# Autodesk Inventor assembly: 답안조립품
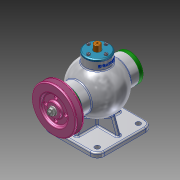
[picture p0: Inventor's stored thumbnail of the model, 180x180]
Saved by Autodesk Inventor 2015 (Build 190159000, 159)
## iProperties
Created: 2025-08
Part Number: 답안조립품
Document SubType Name: Assembly
Designer: USER
Author: USER
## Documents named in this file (15)
- C:\Users\USER\Desktop\750808V1012\답안조립품.iam
- C:\Users\USER\Desktop\750808V1012\본체.ipt
- C:\Users\USER\Desktop\750808V1012\가져온 구성요소\V-벨트풀리\V-벨트풀리.ipt
- C:\Users\USER\Desktop\750808V1012\가져온 구성요소\너트 M8\너트 M8.ipt
- C:\Users\USER\Desktop\750808V1012\가져온 구성요소\뒤커버\뒤커버.ipt
- C:\Users\USER\Desktop\750808V1012\가져온 구성요소\베어링- 6202\베어링- 6202.ipt
- C:\Users\USER\Desktop\750808V1012\가져온 구성요소\볼트 M4 x 12\볼트 M4 x 12.ipt
- C:\Users\USER\Desktop\750808V1012\가져온 구성요소\볼트 M4 x 16\볼트 M4 x 16.ipt
- C:\Users\USER\Desktop\750808V1012\가져온 구성요소\상부커버\상부커버.ipt
- C:\Users\USER\Desktop\750808V1012\가져온 구성요소\슬라이드\슬라이드.ipt
- C:\Users\USER\Desktop\750808V1012\가져온 구성요소\앞커버\앞커버.ipt
- C:\Users\USER\Desktop\750808V1012\가져온 구성요소\오일실 15 30 7\오일실 15 30 7.ipt
- C:\Users\USER\Desktop\750808V1012\가져온 구성요소\칼라\칼라.ipt
- C:\Users\USER\Desktop\750808V1012\가져온 구성요소\키 4 x 4 x 12\키 4 x 4 x 12.ipt
- C:\Users\USER\Desktop\750808V1012\가져온 구성요소\편심축\편심축.ipt
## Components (1 placed, 1 different names)
1. V-벨트풀리:1 — 플러쉬:2
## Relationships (1: Flush 1)
- 플러쉬:2 [Flush]: V-벨트풀리:1
